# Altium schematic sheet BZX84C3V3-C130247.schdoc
size 127 x 101 mm
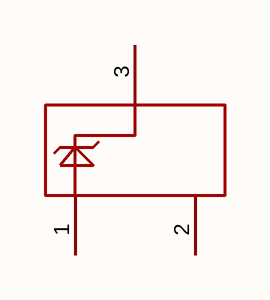
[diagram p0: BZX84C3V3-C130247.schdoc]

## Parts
D?  bzx84c3v3_c130247  [SOT-23_L2.9-W1.3-P1.90-LS2.4-BR]  (value not drawn)

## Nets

Not connected (* = marked no-connect by the designer): D? 1(A) 2(NC) 3(C)

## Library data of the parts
D? = bzx84c3v3_c130247: 二极管配置:1个独立式;稳压值(标称值):3.3V;稳压值(范围):3.1V~3.5V;耗散功率(Pd):300mW;; Manufacturer: CJ(江苏长电/长晶); Symbol: BZX84C3V3-C130247; AddInBom: yes; ModelId: c62791f0466c4ae2a892c056b845b0ca; ModelName: SOT-23-3P_L2.9-W1.3-H1.0-LS2.4-P0.95; ModelTransform: 98.64468,114.173,0,180,0,0,0.001,-0.002,0; Diode Configuration: 1个独立式; Zener Voltage(Nom): 3.3V; Reverse Leakage Current (Ir): 5uA@1V; Pd - Power Dissipation: 300mW; Impedance(Zzt): 95Ω; Impedance(Zzk): 600Ω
